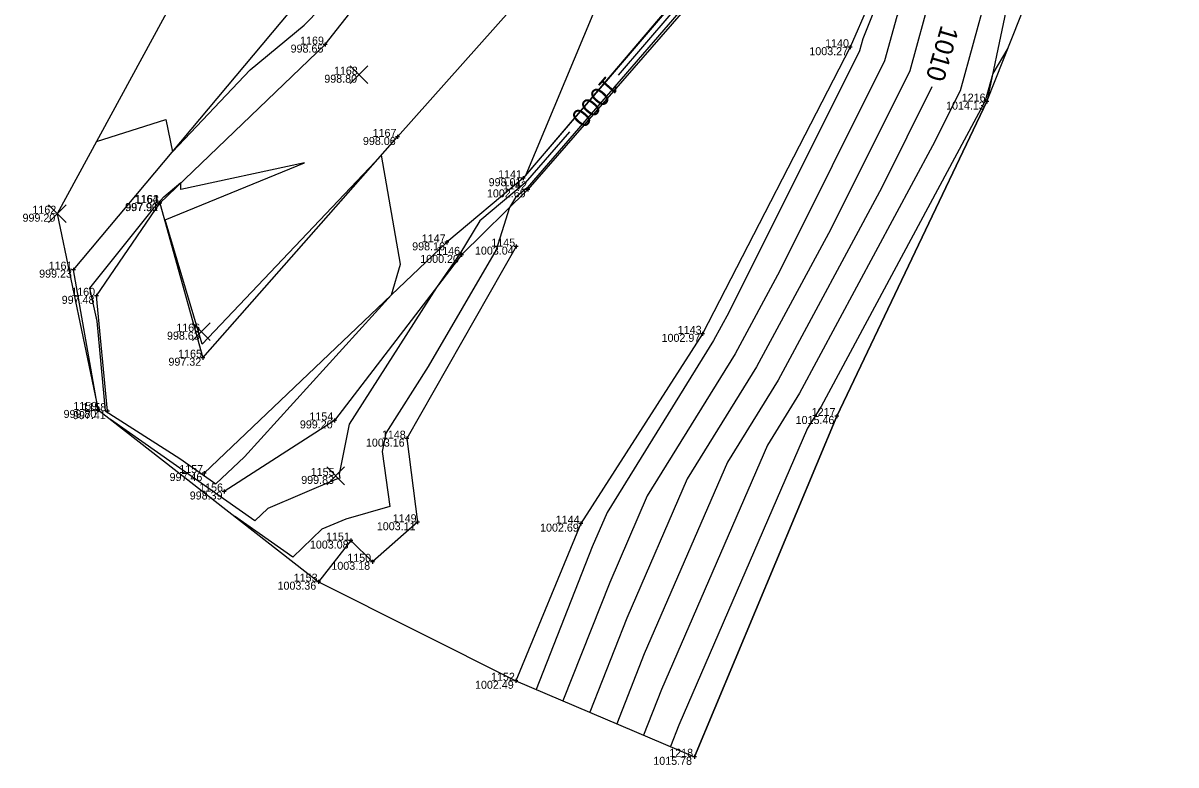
# Model space of a CAD drawing. Extents: x 2354693 to 2355622, y 637071 to 710080.
# Drawn here: x 2355080.8 to 2355253.6, y 708790.5 to 708901.8 of the extents above; entities that cross this region are included whole.
import ezdxf

# ---------------------------------------------------------------- set-up
doc = ezdxf.new("R2010")
doc.units = 0
for name, color, linetype in [('Default', 7, 'Continuous'), ('DT_X_Contour_Major', 7, 'Continuous'), ('DT_X_Contour_Minor', 7, 'Continuous'), ('HY_X_Water_Edge', 7, 'Continuous'), ('SV_X_Break_Lines', 7, 'Continuous'), ('SV_X_Random_Point', 7, 'Continuous'), ('SV_X_Shot_Marker', 7, 'Continuous'), ('SV_X_Text_Elevation', 7, 'Continuous'), ('SV_X_Text_Name', 7, 'Continuous'), ('SV_X_Toe_of_Slope', 7, 'Continuous'), ('SV_X_Top_of_Bank', 7, 'Continuous')]:
    doc.layers.add(name, color=color, linetype=linetype)

msp = doc.modelspace()

# ---------------------------------------------------------------- linework, layer by layer
at = {"layer": 'Default'}
msp.add_lwpolyline([(2355203.89, 709062.28), (2355168.12, 708973.83), (2355139.21, 708949.25), (2355111.34, 708919.92), (2355085.96, 708873.19), (2355092.11, 708843.77), (2355125.13, 708818.02), (2355154.71, 708803.16), (2355181.45, 708791.76), (2355202.79, 708842.86), (2355225.29, 708890), (2355244.12, 708937.56), (2355263.76, 708986.4), (2355330.91, 709003.61)], dxfattribs=at)
msp.add_lwpolyline([(2355203.89, 709062.28), (2355168.12, 708973.83), (2355139.21, 708949.25), (2355111.34, 708919.92), (2355085.96, 708873.19), (2355092.11, 708843.77), (2355125.13, 708818.02), (2355154.71, 708803.16), (2355181.45, 708791.76), (2355202.79, 708842.86), (2355225.29, 708890), (2355244.12, 708937.56), (2355263.76, 708986.4), (2355330.91, 709003.61)], dxfattribs=at)
at = {"layer": 'DT_X_Contour_Major'}
for points in [[(2355232.61, 708971.71), (2355229.37, 708965.55), (2355217.08, 708950.28), (2355209.56, 708941.48), (2355204.21, 708933.75), (2355198.35, 708926.39), (2355185.83, 708912.39), (2355170.05, 708893.95)], [(2355232.61, 708971.71), (2355229.37, 708965.55), (2355217.08, 708950.28), (2355209.56, 708941.48), (2355204.21, 708933.75), (2355198.35, 708926.39), (2355185.83, 708912.39), (2355170.05, 708893.95)], [(2355091.83, 708884), (2355102.22, 708887.3), (2355103.22, 708882.47), (2355114.9, 708894.74), (2355114.9, 708894.74), (2355122.96, 708901.48), (2355138.18, 708917.03), (2355155.58, 708938.33), (2355160.42, 708943.99)], [(2355091.83, 708884), (2355102.22, 708887.3), (2355103.22, 708882.47), (2355114.9, 708894.74), (2355114.9, 708894.74), (2355122.96, 708901.48), (2355138.18, 708917.03), (2355155.58, 708938.33), (2355160.42, 708943.99)], [(2355217.07, 708892.23), (2355209.53, 708877.12), (2355194, 708848.24), (2355186.4, 708835.96), (2355173.94, 708807.2), (2355169.81, 708796.72)], [(2355217.07, 708892.23), (2355209.53, 708877.12), (2355194, 708848.24), (2355186.4, 708835.96), (2355173.94, 708807.2), (2355169.81, 708796.72)], [(2355162.73, 708885.47), (2355156.09, 708877.8), (2355149.29, 708872.12), (2355146.32, 708867.2), (2355142.78, 708862.12), (2355129.72, 708841.65), (2355128.22, 708834.16), (2355128.31, 708833.53), (2355127.8, 708833.39), (2355117.51, 708829.01), (2355115.58, 708827.15), (2355093.95, 708842.34)], [(2355162.73, 708885.47), (2355156.09, 708877.8), (2355149.29, 708872.12), (2355146.32, 708867.2), (2355142.78, 708862.12), (2355129.72, 708841.65), (2355128.22, 708834.16), (2355128.31, 708833.53), (2355127.8, 708833.39), (2355117.51, 708829.01), (2355115.58, 708827.15), (2355093.95, 708842.34)]]:
    msp.add_lwpolyline(points, dxfattribs=at)
at = {"layer": 'DT_X_Contour_Minor'}
for points in [[(2355285.39, 709028.91), (2355262.53, 708987.18), (2355260.94, 708984.64), (2355243.4, 708942.76), (2355240.45, 708936.43), (2355228.87, 708917.33), (2355227.13, 708912.97), (2355221.28, 708891.6), (2355217.16, 708883.36), (2355197.22, 708846.27), (2355192.4, 708838.49), (2355176.54, 708801.86), (2355173.83, 708795)], [(2355285.39, 709028.91), (2355262.53, 708987.18), (2355260.94, 708984.64), (2355243.4, 708942.76), (2355240.45, 708936.43), (2355228.87, 708917.33), (2355227.13, 708912.97), (2355221.28, 708891.6), (2355217.16, 708883.36), (2355197.22, 708846.27), (2355192.4, 708838.49), (2355176.54, 708801.86), (2355173.83, 708795)], [(2355270.62, 709014.28), (2355257.51, 708990.34), (2355249.42, 708977.42), (2355241.28, 708958), (2355229.69, 708933.13), (2355223.8, 708923.4), (2355216.91, 708906.18), (2355213.74, 708894.61), (2355201.89, 708870.88), (2355190.78, 708850.22), (2355180.4, 708833.43), (2355171.35, 708812.54), (2355165.79, 708798.43)], [(2355270.62, 709014.28), (2355257.51, 708990.34), (2355249.42, 708977.42), (2355241.28, 708958), (2355229.69, 708933.13), (2355223.8, 708923.4), (2355216.91, 708906.18), (2355213.74, 708894.61), (2355201.89, 708870.88), (2355190.78, 708850.22), (2355180.4, 708833.43), (2355171.35, 708812.54), (2355165.79, 708798.43)], [(2355263.24, 709006.97), (2355254.99, 708991.91), (2355243.66, 708973.81), (2355240.23, 708965.62), (2355224.31, 708931.48), (2355221.26, 708926.44), (2355211.79, 708902.78), (2355209.96, 708896.11), (2355194.26, 708864.64), (2355187.56, 708852.19), (2355174.4, 708830.91), (2355168.76, 708817.88), (2355161.76, 708800.15)], [(2355263.24, 709006.97), (2355254.99, 708991.91), (2355243.66, 708973.81), (2355240.23, 708965.62), (2355224.31, 708931.48), (2355221.26, 708926.44), (2355211.79, 708902.78), (2355209.96, 708896.11), (2355194.26, 708864.64), (2355187.56, 708852.19), (2355174.4, 708830.91), (2355168.76, 708817.88), (2355161.76, 708800.15)], [(2355250.54, 708994.76), (2355248.29, 708991.85), (2355234.96, 708973.88), (2355224.93, 708954.79), (2355220.91, 708949.79), (2355212.87, 708940.38), (2355209.01, 708932.15), (2355204.99, 708920.04), (2355196.76, 708923.38), (2355186.34, 708911.74), (2355180.74, 708905.19), (2355156.4, 708877.09), (2355154.65, 708875.63), (2355153.75, 708874.12), (2355151.75, 708867.8), (2355141.57, 708850.26), (2355135.2, 708840.27), (2355134.64, 708837.52), (2355135.81, 708829.29), (2355129.21, 708827.4), (2355125.61, 708825.87), (2355121.27, 708821.71), (2355112.53, 708827.85)], [(2355250.54, 708994.76), (2355248.29, 708991.85), (2355234.96, 708973.88), (2355224.93, 708954.79), (2355220.91, 708949.79), (2355212.87, 708940.38), (2355209.01, 708932.15), (2355204.99, 708920.04), (2355196.76, 708923.38), (2355186.34, 708911.74), (2355180.74, 708905.19), (2355156.4, 708877.09), (2355154.65, 708875.63), (2355153.75, 708874.12), (2355151.75, 708867.8), (2355141.57, 708850.26), (2355135.2, 708840.27), (2355134.64, 708837.52), (2355135.81, 708829.29), (2355129.21, 708827.4), (2355125.61, 708825.87), (2355121.27, 708821.71), (2355112.53, 708827.85)], [(2355252.48, 708993.49), (2355242.63, 708977.76), (2355238.16, 708971.94), (2355233.7, 708963.72), (2355223.01, 708938.58), (2355218.93, 708929.83), (2355218.72, 708929.48), (2355206.68, 708899.39), (2355206.19, 708897.61), (2355186.62, 708858.4), (2355184.34, 708854.16), (2355168.4, 708828.38), (2355166.16, 708823.22), (2355157.74, 708801.86)], [(2355252.48, 708993.49), (2355242.63, 708977.76), (2355238.16, 708971.94), (2355233.7, 708963.72), (2355223.01, 708938.58), (2355218.93, 708929.83), (2355218.72, 708929.48), (2355206.68, 708899.39), (2355206.19, 708897.61), (2355186.62, 708858.4), (2355184.34, 708854.16), (2355168.4, 708828.38), (2355166.16, 708823.22), (2355157.74, 708801.86)], [(2355156.25, 708879.08), (2355174.92, 708923.86), (2355185.32, 708928.6), (2355200.49, 708931.8), (2355187.44, 708915.42), (2355185.31, 708913.04), (2355156.25, 708879.08)], [(2355156.25, 708879.08), (2355174.92, 708923.86), (2355185.32, 708928.6), (2355200.49, 708931.8), (2355187.44, 708915.42), (2355185.31, 708913.04), (2355156.25, 708879.08)], [(2355228.46, 708897.99), (2355226.17, 708894.19), (2355225.05, 708890.1), (2355224.8, 708889.6), (2355200.44, 708844.3), (2355198.41, 708841.02), (2355179.13, 708796.52), (2355177.86, 708793.29)], [(2355228.46, 708897.99), (2355226.17, 708894.19), (2355225.05, 708890.1), (2355224.8, 708889.6), (2355200.44, 708844.3), (2355198.41, 708841.02), (2355179.13, 708796.52), (2355177.86, 708793.29)], [(2355134.58, 708881.98), (2355107.67, 708853.63), (2355102.16, 708872.26), (2355123.01, 708880.82), (2355104.48, 708876.81), (2355104.49, 708877.81), (2355101.96, 708875.69), (2355101.95, 708875.7), (2355100.37, 708874.04), (2355100.37, 708874.03), (2355090.81, 708862.04), (2355091.89, 708857.06), (2355093.15, 708843.63), (2355104.33, 708836.49), (2355109.74, 708832.7), (2355114.05, 708836.75), (2355136.07, 708861.03), (2355137.41, 708865.62), (2355134.58, 708881.98)], [(2355134.58, 708881.98), (2355107.67, 708853.63), (2355102.16, 708872.26), (2355123.01, 708880.82), (2355104.48, 708876.81), (2355104.49, 708877.81), (2355101.96, 708875.69), (2355101.95, 708875.7), (2355100.37, 708874.04), (2355100.37, 708874.03), (2355090.81, 708862.04), (2355091.89, 708857.06), (2355093.15, 708843.63), (2355104.33, 708836.49), (2355109.74, 708832.7), (2355114.05, 708836.75), (2355136.07, 708861.03), (2355137.41, 708865.62), (2355134.58, 708881.98)]]:
    msp.add_lwpolyline(points, dxfattribs=at)
at = {"layer": 'HY_X_Water_Edge'}
for points in [[(2355272.75, 709215.1), (2355272.74, 709215.09), (2355269.55, 709175.73), (2355269.77, 709147.81), (2355269.19, 709105.65), (2355274.67, 709084.44), (2355274.45, 709045.7), (2355249.64, 708995.53), (2355233.3, 708975.07), (2355214.48, 708950.61), (2355202.85, 708934.67), (2355185.21, 708913.18), (2355155.78, 708878.52), (2355144.35, 708868.9), (2355107.99, 708834.31)], [(2355093.48, 708843.59), (2355091.82, 708860.88), (2355101.34, 708874.79), (2355126.1, 708898.55), (2355156.73, 708937.57), (2355180.39, 708963.52), (2355184.45, 708982.97), (2355223.4, 709017.99), (2355237.5, 709039.04), (2355220.47, 709066.41), (2355205.69, 709069.16)]]:
    msp.add_lwpolyline(points, dxfattribs=at)
at = {"layer": 'SV_X_Break_Lines'}
msp.add_lwpolyline([(2355154.74, 708868.26), (2355138.38, 708839.47), (2355139.98, 708826.93), (2355133.2, 708821), (2355129.97, 708824.18), (2355125.13, 708818.02)], dxfattribs=at)
at = {"layer": 'SV_X_Random_Point'}
for p, q in [((2355129.85, 708892.7), (2355132.52, 708895.37)), ((2355129.85, 708895.37), (2355132.52, 708892.7)), ((2355084.63, 708871.85), (2355087.3, 708874.52)), ((2355084.63, 708874.52), (2355087.3, 708871.85)), ((2355106.23, 708854.17), (2355108.89, 708856.84)), ((2355106.23, 708856.84), (2355108.89, 708854.17)), ((2355126.35, 708832.55), (2355129.02, 708835.22)), ((2355126.35, 708835.22), (2355129.02, 708832.55))]:
    msp.add_line(p, q, dxfattribs=at)
at = {"layer": 'SV_X_Shot_Marker'}
for p, q in [((2355126.1, 708898.85), (2355126.1, 708898.25)), ((2355126.4, 708898.55), (2355125.8, 708898.55)), ((2355205.13, 708898.16), (2355204.53, 708898.16)), ((2355204.83, 708898.46), (2355204.83, 708897.86)), ((2355225.29, 708890.3), (2355225.29, 708889.7)), ((2355225.59, 708890), (2355224.99, 708890)), ((2355136.97, 708885), (2355136.97, 708884.4)), ((2355137.27, 708884.7), (2355136.67, 708884.7)), ((2355156.08, 708878.52), (2355155.48, 708878.52)), ((2355155.78, 708878.82), (2355155.78, 708878.22)), ((2355156.8, 708876.84), (2355156.2, 708876.84)), ((2355156.5, 708877.14), (2355156.5, 708876.54)), ((2355101.62, 708874.78), (2355101.02, 708874.78)), ((2355101.64, 708874.79), (2355101.04, 708874.79)), ((2355101.32, 708875.08), (2355101.32, 708874.48)), ((2355101.34, 708875.09), (2355101.34, 708874.49)), ((2355144.65, 708868.9), (2355144.05, 708868.9)), ((2355144.35, 708869.2), (2355144.35, 708868.6)), ((2355155.04, 708868.26), (2355154.44, 708868.26)), ((2355154.74, 708868.56), (2355154.74, 708867.96)), ((2355146.83, 708867.02), (2355146.23, 708867.02)), ((2355146.53, 708867.32), (2355146.53, 708866.72)), ((2355088.7, 708864.8), (2355088.1, 708864.8)), ((2355088.4, 708865.1), (2355088.4, 708864.5)), ((2355092.12, 708860.88), (2355091.52, 708860.88)), ((2355091.82, 708861.18), (2355091.82, 708860.58)), ((2355182.98, 708855.18), (2355182.38, 708855.18)), ((2355182.68, 708855.48), (2355182.68, 708854.88)), ((2355108.1, 708851.6), (2355107.5, 708851.6)), ((2355107.8, 708851.9), (2355107.8, 708851.3)), ((2355092.41, 708843.77), (2355091.81, 708843.77)), ((2355092.11, 708844.07), (2355092.11, 708843.47)), ((2355093.78, 708843.59), (2355093.18, 708843.59)), ((2355093.48, 708843.89), (2355093.48, 708843.29)), ((2355127.83, 708842.2), (2355127.23, 708842.2)), ((2355127.53, 708842.5), (2355127.53, 708841.9)), ((2355203.09, 708842.86), (2355202.49, 708842.86)), ((2355202.79, 708843.16), (2355202.79, 708842.56)), ((2355138.68, 708839.47), (2355138.08, 708839.47)), ((2355138.38, 708839.77), (2355138.38, 708839.17)), ((2355108.29, 708834.31), (2355107.69, 708834.31)), ((2355107.99, 708834.61), (2355107.99, 708834.01)), ((2355111.29, 708831.54), (2355110.69, 708831.54)), ((2355110.99, 708831.84), (2355110.99, 708831.24)), ((2355140.28, 708826.93), (2355139.68, 708826.93)), ((2355139.98, 708827.23), (2355139.98, 708826.63)), ((2355164.76, 708826.72), (2355164.16, 708826.72)), ((2355164.46, 708827.02), (2355164.46, 708826.42)), ((2355130.27, 708824.18), (2355129.67, 708824.18)), ((2355129.97, 708824.48), (2355129.97, 708823.88)), ((2355133.2, 708821.3), (2355133.2, 708820.7)), ((2355133.5, 708821), (2355132.9, 708821)), ((2355125.43, 708818.02), (2355124.83, 708818.02)), ((2355125.13, 708818.32), (2355125.13, 708817.72)), ((2355155.01, 708803.16), (2355154.41, 708803.16)), ((2355154.71, 708803.46), (2355154.71, 708802.86)), ((2355181.75, 708791.76), (2355181.15, 708791.76)), ((2355181.45, 708792.06), (2355181.45, 708791.46))]:
    msp.add_line(p, q, dxfattribs=at)
at = {"layer": 'SV_X_Toe_of_Slope'}
for points in [[(2355342.79, 709267.27), (2355319.66, 709264.93), (2355304.72, 709256.21), (2355286.48, 709242.45), (2355272.74, 709215.09), (2355269.55, 709175.73), (2355269.77, 709147.81), (2355269.19, 709105.65), (2355274.67, 709084.44), (2355274.45, 709045.7), (2355249.64, 708995.53), (2355233.3, 708975.07), (2355214.48, 708950.61), (2355202.85, 708934.67), (2355185.21, 708913.18), (2355155.78, 708878.52), (2355144.35, 708868.9), (2355107.99, 708834.31)], [(2355093.48, 708843.59), (2355091.82, 708860.88), (2355101.34, 708874.79), (2355126.1, 708898.55), (2355156.73, 708937.57), (2355180.39, 708963.52), (2355184.45, 708982.97), (2355223.4, 709017.99), (2355237.5, 709039.04), (2355220.47, 709066.41), (2355205.69, 709069.16)], [(2355239.46, 708971.18), (2355218.53, 708929.71), (2355204.83, 708898.16), (2355182.68, 708855.18), (2355164.46, 708826.72), (2355154.71, 708803.16)], [(2355101.32, 708874.78), (2355107.8, 708851.6), (2355136.97, 708884.7), (2355173.28, 708925.57), (2355185.4, 708941.09), (2355173.48, 708955.39)]]:
    msp.add_lwpolyline(points, dxfattribs=at)
at = {"layer": 'SV_X_Top_of_Bank'}
for points in [[(2355273.36, 709199.07), (2355271.07, 709175.55), (2355271.92, 709154.64), (2355272.23, 709141.56), (2355270.63, 709105.68), (2355275.83, 709084.35), (2355276.25, 709045.62), (2355250.74, 708994.59), (2355235.32, 708973.62), (2355222.78, 708949.56), (2355205.08, 708933.16), (2355186.58, 708911.43), (2355156.5, 708876.84), (2355146.53, 708867.02), (2355127.53, 708842.2), (2355110.99, 708831.54)], [(2355092.11, 708843.77), (2355088.4, 708864.8), (2355120.83, 708903.46), (2355153.14, 708939.92), (2355177.02, 708968.14), (2355183, 708983.64), (2355218.52, 709022.16), (2355226.6, 709031.85), (2355225.79, 709044.32), (2355216.32, 709062.32), (2355203.89, 709062.28)], [(2355286.26, 709029.77), (2355263.76, 708986.4), (2355244.12, 708937.56), (2355230.59, 708915.27), (2355225.29, 708890), (2355202.79, 708842.86), (2355181.45, 708791.76)]]:
    msp.add_lwpolyline(points, dxfattribs=at)

# ---------------------------------------------------------------- texts
at = {"layer": 'DT_X_Contour_Major'}
for s, rotation, p in [('1010', 253.7056, (2355218.45, 708901.58)), ('1010', 253.7056, (2355218.45, 708901.58)), ('1000', 229.1875, (2355168.25, 708894)), ('1000', 229.1875, (2355168.25, 708894))]:
    msp.add_text(s, height=2.8, rotation=rotation, dxfattribs=at).set_placement(p)
at = {"layer": 'SV_X_Text_Elevation'}
for s, p in [('998.65', (2355120.94, 708897.35)), ('1003.27', (2355198.69, 708896.96)), ('998.80', (2355125.99, 708892.83)), ('1014.13', (2355219.18, 708888.8)), ('998.06', (2355131.78, 708883.5)), ('998.01', (2355150.62, 708877.32)), ('1002.69', (2355150.37, 708875.64)), ('997.90', (2355096.12, 708873.58)), ('997.91', (2355096.18, 708873.59)), ('999.20', (2355080.76, 708871.99)), ('998.16', (2355139.16, 708867.7)), ('1003.04', (2355148.57, 708867.06)), ('1000.20', (2355140.37, 708865.82)), ('999.23', (2355083.25, 708863.6)), ('997.48', (2355086.63, 708859.68)), ('998.63', (2355102.41, 708854.3)), ('1002.97', (2355176.54, 708853.98)), ('997.32', (2355102.63, 708850.4)), ('999.80', (2355086.91, 708842.57)), ('997.41', (2355088.32, 708842.39)), ('999.20', (2355122.33, 708841)), ('1015.46', (2355196.64, 708841.66)), ('1003.16', (2355132.23, 708838.27)), ('997.46', (2355102.8, 708833.11)), ('999.83', (2355122.53, 708832.68)), ('998.39', (2355105.82, 708830.34)), ('1003.11', (2355133.86, 708825.73)), ('1002.69', (2355158.33, 708825.52)), ('1003.08', (2355123.83, 708822.98)), ('1003.18', (2355127.05, 708819.8)), ('1003.36', (2355118.98, 708816.82)), ('1002.49', (2355148.58, 708801.96)), ('1015.78', (2355175.3, 708790.56))]:
    msp.add_text(s, height=1.2, dxfattribs=at).set_placement(p)
at = {"layer": 'SV_X_Text_Name'}
for s, p in [('1169', (2355122.36, 708898.55)), ('1140', (2355201.06, 708898.16)), ('1168', (2355127.43, 708894.03)), ('1216', (2355221.53, 708890)), ('1167', (2355133.23, 708884.7)), ('1141', (2355152.05, 708878.52)), ('1142', (2355152.78, 708876.84)), ('1164', (2355097.55, 708874.78)), ('1163', (2355097.63, 708874.79)), ('1162', (2355082.24, 708873.19)), ('1147', (2355140.6, 708868.9)), ('1145', (2355151.02, 708868.26)), ('1146', (2355142.77, 708867.02)), ('1161', (2355084.67, 708864.8)), ('1160', (2355088.06, 708860.88)), ('1166', (2355103.8, 708855.5)), ('1143', (2355178.97, 708855.18)), ('1165', (2355104.08, 708851.6)), ('1159', (2355088.38, 708843.77)), ('1158', (2355089.73, 708843.59)), ('1217', (2355199.04, 708842.86)), ('1154', (2355123.76, 708842.2)), ('1148', (2355134.62, 708839.47)), ('1157', (2355104.25, 708834.31)), ('1155', (2355123.96, 708833.88)), ('1156', (2355107.23, 708831.54)), ('1149', (2355136.25, 708826.93)), ('1144', (2355160.68, 708826.72)), ('1151', (2355126.25, 708824.18)), ('1150', (2355129.43, 708821)), ('1153', (2355121.41, 708818.02)), ('1152', (2355150.98, 708803.16)), ('1218', (2355177.69, 708791.76))]:
    msp.add_text(s, height=1.2, dxfattribs=at).set_placement(p)

doc.saveas('drawing.dxf')
